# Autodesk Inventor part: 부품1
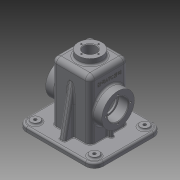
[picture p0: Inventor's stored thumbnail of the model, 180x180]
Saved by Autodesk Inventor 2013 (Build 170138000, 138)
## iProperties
Created: 2016-01
Part Number: 부품1
Material: 일반
Document SubType Name: Modeling
Designer: Administrator
Density: 1 g/cm^3
Author: Administrator
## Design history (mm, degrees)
sketch "스케치1"
  geometry: L1 (-65, 57.5)-(65, 57.5); L2 (65, 57.5)-(65, -57.5); L3 (65, -57.5)-(-65, -57.5); L4 (-65, -57.5)-(-65, 57.5); 3 further points
  constraints: 8 end point, 2 midpoint, 2 parallel, 1 horizontal, 1 horizontal alignment, 1 perpendicular, 1 vertical alignment
  dimensions: "d0" = 130 distance of L1.start L1.end; "d2" = 115 distance of L1.end L2.end
extrude "돌출1" new body sketch "스케치1" distance "d3" = 8; taper "d4" = 0 deg
sketch "스케치2"
  geometry: L1 (60, -52.5)-(-60, -52.5); L2 (-60, -52.5)-(-60, 52.5); L3 (-60, 52.5)-(60, 52.5); L4 (60, 52.5)-(60, -52.5); 3 further points
  constraints: 8 end point, 2 midpoint, 2 parallel, 1 horizontal, 1 horizontal alignment, 1 perpendicular, 1 vertical alignment
  dimensions: "d5" = 120 distance of L1.start L1.end; "d7" = 105 distance of L1.end L2.end
extrude "돌출2" join sketch "스케치2" distance "d8" = 2; taper "d9" = 0 deg
sketch "스케치3"
  geometry: L1 (-32.5, 32.5)-(32.5, 32.5); L2 (32.5, 32.5)-(32.5, -32.5); L3 (32.5, -32.5)-(-32.5, -32.5); L4 (-32.5, -32.5)-(-32.5, 32.5); 3 further points
  constraints: 8 end point, 2 midpoint, 2 parallel, 1 horizontal, 1 horizontal alignment, 1 perpendicular, 1 vertical alignment
  dimensions: "d10" = 65 distance of L1.start L1.end; "d12" = 65 distance of L1.end L2.end
extrude "돌출3" join sketch "스케치3" distance "d13" = 100; taper "d14" = 0 deg
fillet "모깎기1" dims "d15" = 15
sketch "스케치4"
  geometry: C1 r 7.5 at (-50, 42.5); C2 r 7.5 at (-50, -42.5); C3 r 7.5 at (50, -42.5); C4 r 7.5 at (50, 42.5); A1 r 15 centre (-50, 42.5) between (-50, 57.5) and (-65, 42.5) reference; A2 r 15 centre (-50, -42.5) between (-65, -42.5) and (-50, -57.5) reference; A3 r 15 centre (50, -42.5) between (50, -57.5) and (65, -42.5) reference; A4 r 15 centre (50, 42.5) between (65, 42.5) and (50, 57.5) reference; 1 further point
  constraints: 4 centre point, 4 coincident
  dimensions: "d16" = 15 diameter of C1; "d17" = 15 diameter of C2; "d18" = 15 diameter of C3; "d19" = 15 diameter of C4
extrude "돌출4" join sketch "스케치4" distance "d20" = 3; taper "d21" = 0 deg
hole "구멍1" diameter "d25" = 5; stored, may be unused: countersink angle "d29" = 90 deg, drill point angle "d31" = 0 deg; dims "d23" = 10, "d24" = 10, "d26" = 6, "d27" = 4, "d28" = 2, "d30" = 8
hole "구멍2" diameter "d34" = 5; stored, may be unused: countersink angle "d38" = 90 deg, drill point angle "d40" = 0 deg; dims "d32" = 10, "d33" = 10, "d35" = 6, "d36" = 4, "d37" = 2, "d39" = 8
hole "구멍3" diameter "d43" = 5; stored, may be unused: countersink angle "d47" = 90 deg, drill point angle "d49" = 0 deg; dims "d41" = 10, "d42" = 10, "d44" = 6, "d45" = 4, "d46" = 2, "d48" = 8
hole "구멍4" diameter "d52" = 5; stored, may be unused: countersink angle "d56" = 90 deg, drill point angle "d58" = 0 deg; dims "d50" = 10, "d51" = 10, "d53" = 6, "d54" = 4, "d55" = 2, "d57" = 8
sketch "스케치6"
  geometry: L1 (-27.5, -27.5)-(27.5, -27.5); L2 (27.5, -27.5)-(27.5, 27.5); L3 (27.5, 27.5)-(-27.5, 27.5); L4 (-27.5, 27.5)-(-27.5, -27.5); 3 further points
  constraints: 8 end point, 2 midpoint, 2 parallel, 1 horizontal, 1 horizontal alignment, 1 perpendicular, 1 vertical alignment
  dimensions: "d60" = 55 distance of L3.end L1.start; "d62" = 55 distance of L2.end L3.end
extrude "돌출5" cut sketch "스케치6" distance "d63" = 105; taper "d64" = 0 deg
sketch "스케치7"
  geometry: L1 (32.5, 108)-(32.5, 8) reference; L2 (32.5, 8)-(57.5, 8) reference; L3 (57.5, 8)-(57.5, 0) reference; L4 (57.5, 0)-(52.5, 0) reference; L5 (52.5, 0)-(52.5, -2) reference; L6 (52.5, -2)-(27.5, -2) reference; L7 (27.5, -2)-(27.5, 103) reference; L8 (27.5, 103)-(-27.5, 103) reference; L9 (-27.5, 103)-(-27.5, -2) reference; L10 (-27.5, -2)-(-52.5, -2) reference; L11 (-52.5, -2)-(-52.5, 0) reference; L12 (-52.5, 0)-(-57.5, 0) reference; L13 (-57.5, 0)-(-57.5, 8) reference; L14 (-57.5, 8)-(-32.5, 8) reference; L15 (-32.5, 8)-(-32.5, 108) reference; L16 (-32.5, 108)-(32.5, 108) reference; L17 (-57.5, 8)-(-42.5, 8) reference; L18 (-48.184, 8)-(-32.5, 87.642); L19 (-32.5, 8)-(-32.5, 108) reference; 1 further point
  constraints: 2 end point, 2 point on line
feature "리브1" sketch "스케치7" dims "d65" = 1, "d66" = 10, "d67" = 0, "d68" = 0, "d69" = 1, "d70" = 1
sketch "스케치8"
  geometry: L1 (8, 90)-(8, 85) reference; L2 (8, 85)-(10, 85) reference; L3 (10, 85)-(10, -20) reference; L4 (10, -20)-(8, -20) reference; L5 (8, -20)-(8, -25) reference; L6 (8, -25)-(0, -25) reference; L7 (0, -25)-(0, 0) reference; L8 (0, 0)-(0, 65) reference; L9 (0, 65)-(0, 90) reference; L10 (0, 90)-(8, 90) reference; L11 (0, 0)-(-100, 0) reference; L12 (-100, 0)-(-100, 65) reference; L13 (-100, 65)-(0, 65) reference; L14 (10, 85)-(10, -20) reference; L15 (10, 32.5)-(-45, 32.5); C1 r 27.5 at (-45, 32.5); 1 further point
  constraints: 2 end point, 1 centre point, 1 coincident, 1 horizontal, 1 midpoint
  dimensions: "d71" = 55 distance of L15.start L15.end; "d72" = 55 diameter of C1
extrude "돌출6" join sketch "스케치8" distance "d73" = 15; taper "d74" = 0 deg
sketch "스케치9"
  geometry: C1 r 27.5 at (0, 0) reference; 1 further point
hole "구멍5" sketch "스케치9" at (0, 0) diameter "d75" = 30; stored, may be unused: countersink angle "d79" = 82 deg, drill point angle "d81" = 0 deg; dims "d76" = 6, "d77" = 35, "d78" = 17, "d80" = 30
sketch "스케치11"
  geometry: L1 (0, 0)-(-21, 0); C1 r 27.5 at (0, 0) reference; 1 further point
  constraints: 2 end point, 1 horizontal
  dimensions: "d82" = 21 distance of L1.start L1.end
hole "구멍6" sketch "스케치11" at (-21, 0) diameter "d83" = 3.242; stored, may be unused: countersink angle "d87" = 82 deg, drill point angle "d89" = 118 deg; dims "d84" = 8, "d85" = 35, "d86" = 17, "d88" = 10
sketch "스케치13"
  geometry: L1 (27.5, 103)-(-27.5, 103) reference; L2 (-27.5, 103)-(-27.5, 68) reference; L3 (-27.5, 68)-(-30.5, 68) reference; L4 (-30.5, 68)-(-30.5, 70.5) reference; L5 (-30.5, 70.5)-(-47.5, 70.5) reference; L6 (-47.5, 70.5)-(-47.5, 72.379) reference; L7 (-47.5, 72.379)-(-37.5, 72.379) reference; L8 (-37.5, 72.379)-(-36.526, 74) reference; L9 (-36.526, 74)-(-37.5, 75.621) reference; L10 (-37.5, 75.621)-(-47.5, 75.621) reference; L11 (-47.5, 75.621)-(-47.5, 80.5) reference; L12 (-47.5, 80.5)-(-32.5, 80.5) reference; L13 (-32.5, 80.5)-(-32.5, 108) reference; L14 (-32.5, 108)-(32.5, 108) reference; L15 (32.5, 108)-(32.5, 80.5) reference; L16 (32.5, 80.5)-(47.5, 80.5) reference; L17 (47.5, 80.5)-(47.5, 75.621) reference; L18 (47.5, 75.621)-(37.5, 75.621) reference; L19 (37.5, 75.621)-(36.526, 74) reference; L20 (36.526, 74)-(37.5, 72.379) reference; L21 (37.5, 72.379)-(47.5, 72.379) reference; L22 (47.5, 72.379)-(47.5, 70.5) reference; L23 (47.5, 70.5)-(30.5, 70.5) reference; L24 (30.5, 70.5)-(30.5, 68) reference; L25 (30.5, 68)-(27.5, 68) reference; L26 (27.5, 68)-(27.5, 103) reference; L27 (65, 0)-(60, 0) reference; L28 (60, 0)-(60, -2) reference; L29 (60, -2)-(27.5, -2) reference; L30 (27.5, -2)-(27.5, 38) reference; L31 (27.5, 38)-(30.5, 38) reference; L32 (30.5, 38)-(30.5, 35.5) reference; L33 (30.5, 35.5)-(47.5, 35.5) reference; L34 (47.5, 35.5)-(47.5, 33.621) reference; L35 (47.5, 33.621)-(37.5, 33.621) reference; L36 (37.5, 33.621)-(36.526, 32) reference; L37 (36.526, 32)-(37.5, 30.379) reference; L38 (37.5, 30.379)-(47.5, 30.379) reference; L39 (47.5, 30.379)-(47.5, 25.5) reference; L40 (47.5, 25.5)-(32.5, 25.5) reference; L41 (32.5, 25.5)-(32.5, 8) reference; L42 (32.5, 8)-(65, 8) reference; L43 (65, 8)-(65, 0) reference; L44 (-60, 0)-(-65, 0) reference; L45 (-65, 0)-(-65, 8) reference; L46 (-65, 8)-(-32.5, 8) reference; L47 (-32.5, 8)-(-32.5, 25.5) reference; L48 (-32.5, 25.5)-(-47.5, 25.5) reference; L49 (-47.5, 25.5)-(-47.5, 30.379) reference; L50 (-47.5, 30.379)-(-37.5, 30.379) reference; L51 (-37.5, 30.379)-(-36.526, 32) reference; L52 (-36.526, 32)-(-37.5, 33.621) reference; L53 (-37.5, 33.621)-(-47.5, 33.621) reference; L54 (-47.5, 33.621)-(-47.5, 35.5) reference; L55 (-47.5, 35.5)-(-30.5, 35.5) reference; L56 (-30.5, 35.5)-(-30.5, 38) reference; L57 (-30.5, 38)-(-27.5, 38) reference; L58 (-27.5, 38)-(-27.5, -2) reference; L59 (-27.5, -2)-(-60, -2) reference; L60 (-60, -2)-(-60, 0) reference; L61 (-50, 8)-(50, 8) reference; L62 (39, 8)-(39, 25.5); 1 further point
  constraints: 2 end point, 2 point on line, 1 vertical
feature "리브2" sketch "스케치13" dims "d93" = 1, "d94" = 6, "d95" = 0, "d96" = 0, "d97" = 1, "d98" = 1
sketch "스케치14"
  geometry: C1 r 20 at (0, 0); 1 further point
  constraints: 1 centre point, 1 coincident
  dimensions: "d99" = 40 diameter of C1
extrude "돌출7" join sketch "스케치14" distance "d100" = 10; taper "d101" = 0 deg
hole "구멍7" diameter "d104" = 21; stored, may be unused: countersink angle "d108" = 82 deg, drill point angle "d110" = 0 deg; dims "d102" = 10, "d103" = 10, "d105" = 8, "d106" = 35, "d107" = 17, "d109" = 10
sketch "스케치16"
  geometry: L1 (0, 0)-(14.5, 0); C1 r 20 at (0, 0) reference
  constraints: 2 end point, 1 horizontal
  dimensions: "d111" = 14.5 distance of L1.start L1.end
hole "구멍8" sketch "스케치16" at (14.5, 0) diameter "d112" = 2.459; stored, may be unused: countersink angle "d116" = 82 deg, drill point angle "d118" = 0 deg; dims "d113" = 7, "d114" = 35, "d115" = 17, "d117" = 9
fillet "모깎기2" dims "d122" = 8
fillet "모깎기3" dims "d123" = 8
fillet "모깎기5" dims "d125" = 10
fillet "모깎기7" dims "d127" = 0.3
chamfer "모따기1" distance "d128" = 1; stored, may be unused: second distance "d129" = 2, angle "d130" = 45 deg
sketch "스케치17"
  geometry: L1 (53, -52.5)-(53, -57.5) reference; L2 (53, -57.5)-(45, -57.5) reference; L3 (45, -57.5)-(45, -24.5) reference; L4 (45, -24.5)-(45, -3) reference; L5 (45, -3)-(27.336, -3) reference; L6 (-12.49, -24.5)-(-47, -24.5) reference; L7 (-47, -24.5)-(-47, 24.5) reference; L8 (-12.49, 24.5)-(-47, 24.5) reference; L9 (45, 24.5)-(12.49, 24.5) reference; L10 (45, 3)-(45, 24.5) reference; L11 (27.336, 3)-(45, 3) reference; L12 (55, -52.5)-(53, -52.5) reference; L13 (55, 52.5)-(55, -52.5) reference; L14 (53, 52.5)-(55, 52.5) reference; L15 (53, 57.5)-(53, 52.5) reference; L16 (45, 57.5)-(53, 57.5) reference; L17 (45, 24.5)-(45, 57.5) reference; L18 (45, -24.5)-(12.49, -24.5) reference; L19 (-65, -1.229)-(-65, 1.23) reference; L20 (-65, 0)-(-38, 0); C1 r 17.5 at (0, 0) reference; A1 r 27.5 centre (0, 0) between (-12.49, 24.5) and (-12.49, -24.5) reference; A2 r 27.5 centre (0, 0) between (12.49, -24.5) and (27.336, -3) reference; A3 r 27.5 centre (0, 0) between (-12.49, -24.5) and (12.49, -24.5) reference; A4 r 27.5 centre (0, 0) between (12.49, 24.5) and (-12.49, 24.5) reference; A5 r 27.5 centre (0, 0) between (27.336, 3) and (12.49, 24.5) reference; A6 r 27.5 centre (0, 0) between (-12.49, 24.5) and (-12.49, -24.5) reference; 2 further points
  constraints: 2 end point, 1 coincident, 1 horizontal, 1 horizontal alignment, 1 midpoint, 1 other
  dimensions: "d131" = 27 distance of L20.start L20.end
feature "엠보싱1" sketch "스케치17" dims "d10" = 65, "d12" = 65, "d79" = 82 deg, "d95" = 0, "d103" = 10, "d109" = 10, "d132" = 0.5, "d133" = 0, "d140" = 3, "d144" = 3, "d146" = 3
fillet "모깎기8" dims "d134" = 3
fillet "모깎기9" dims "d135" = 3
fillet "모깎기14" dims "d140" = 3
fillet "모깎기15" dims "d141" = 3
fillet "모깎기16" dims "d142" = 3
fillet "모깎기17" dims "d143" = 3
fillet "모깎기18" dims "d144" = 3
fillet "모깎기19" dims "d145" = 1
fillet "모깎기20" dims "d146" = 3
fillet "모깎기21" dims "d147" = 3
fillet "모깎기22" dims "d148" = 3
node "솔리드1"
mirror "대칭1"
pattern_circular "원형 패턴1" dims angle "d91" = 360 deg
mirror "대칭2"
mirror "대칭3"
pattern_circular "원형 패턴2" dims angle "d120" = 360 deg
node "절단 모서리 투영1"
node "절단 모서리 투영2"
node "절단 모서리 투영3"
node "절단 모서리 투영4"
